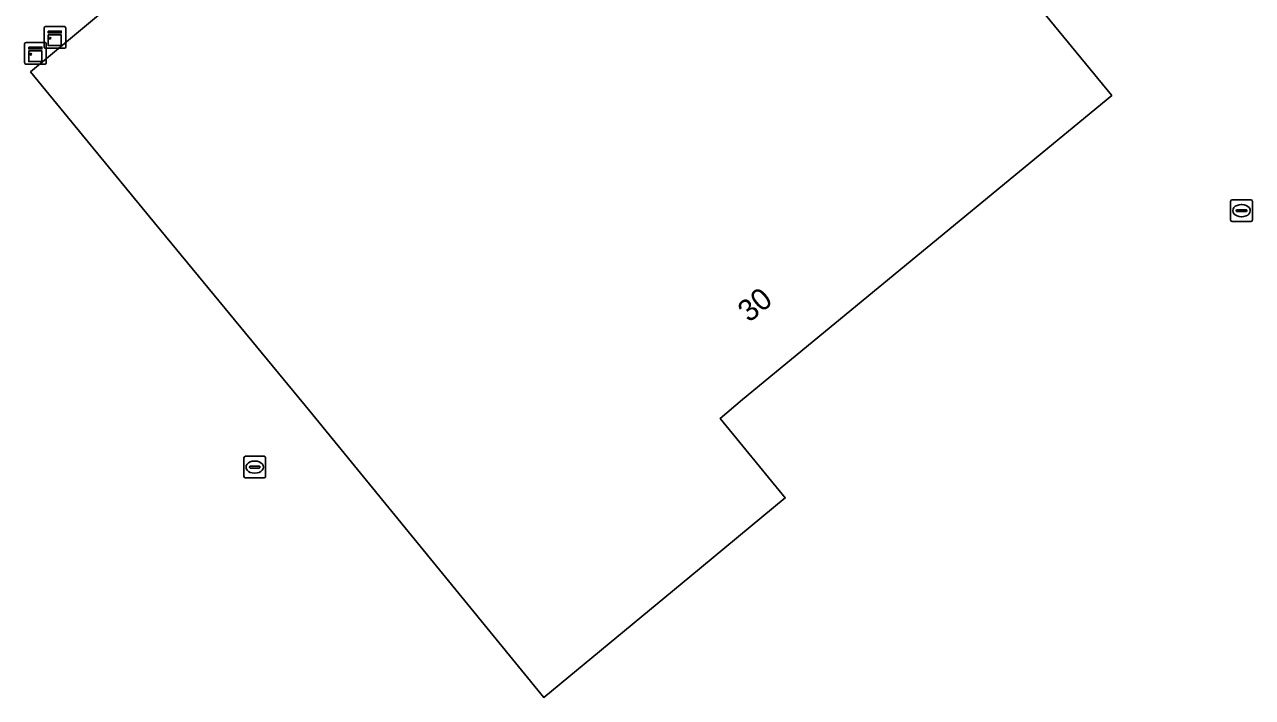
# Model space of a CAD drawing. Extents: x 156141 to 158132, y 385651 to 388333.
# Drawn here: x 157149.6 to 157206.1, y 386304.7 to 386335.6 of the extents above; entities that cross this region are included whole.
import ezdxf

# ---------------------------------------------------------------- set-up
doc = ezdxf.new("R2010")
doc.units = 0
for name, color, linetype in [('IMGEO_Erf', 7, 'Continuous'), ('IMGEO_Kast', 7, 'Continuous'), ('IMGEO_Kolk', 7, 'Continuous'), ('IMGEO_Pand', 7, 'Continuous'), ('IMGEO_Pand_nummerreeks', 7, 'Continuous'), ('IMGEO_Rioolput', 7, 'Continuous')]:
    doc.layers.add(name, color=color, linetype=linetype)

msp = doc.modelspace()

# ---------------------------------------------------------------- linework, layer by layer
at = {"layer": 'IMGEO_Erf'}
msp.add_lwpolyline([(157149.922, 386333.398), (157160.041, 386341.853), (157161.117, 386342.776), (157162.133, 386343.594), (157165.226, 386346.119), (157167.948, 386348.366), (157171.025, 386350.88), (157173.757, 386353.14), (157176.864, 386355.643), (157177.859, 386356.521), (157178.954, 386357.421), (157199.602, 386332.321), (157182.63, 386318.349), (157181.607, 386317.478), (157184.594, 386313.821), (157180.217, 386310.192), (157173.499, 386304.656), (157162.753, 386317.816), (157155.393, 386326.726)], close=True, dxfattribs=at)
at = {"layer": 'IMGEO_Kast'}
for p, q in [((157150.538, 386334.557), (157150.538, 386335.398)), ((157150.538, 386335.398), (157150.538, 386334.557)), ((157150.613, 386335.482), (157151.454, 386335.482)), ((157151.454, 386335.482), (157150.613, 386335.482)), ((157151.538, 386335.407), (157151.538, 386334.566)), ((157151.538, 386334.566), (157151.538, 386335.407)), ((157149.644, 386333.824), (157149.644, 386334.665)), ((157149.644, 386334.665), (157149.644, 386333.824)), ((157149.719, 386334.749), (157150.56, 386334.749)), ((157150.56, 386334.749), (157149.719, 386334.749)), ((157151.463, 386334.482), (157150.622, 386334.482)), ((157150.622, 386334.482), (157151.463, 386334.482)), ((157150.644, 386334.674), (157150.644, 386333.833)), ((157150.644, 386333.833), (157150.644, 386334.674)), ((157150.569, 386333.749), (157149.728, 386333.749)), ((157149.728, 386333.749), (157150.569, 386333.749))]:
    msp.add_line(p, q, dxfattribs=at)
for points in [[(157150.733, 386335.272), (157151.333, 386335.272), (157151.333, 386335.187), (157150.733, 386335.187), (157150.733, 386335.272)], [(157150.733, 386335.097), (157151.333, 386335.097), (157151.333, 386334.608), (157150.733, 386334.608), (157150.733, 386335.097)], [(157149.839, 386334.539), (157150.439, 386334.539), (157150.439, 386334.454), (157149.839, 386334.454), (157149.839, 386334.539)], [(157149.839, 386334.364), (157150.439, 386334.364), (157150.439, 386333.875), (157149.839, 386333.875), (157149.839, 386334.364)]]:
    msp.add_lwpolyline(points, dxfattribs=at)
for centre in [(157150.817, 386334.946), (157149.923, 386334.213)]:
    msp.add_circle(centre, 0.0377, dxfattribs=at)
for centre, start, end in [((157150.616, 386335.404), 92.4484, 184.2845), ((157150.616, 386335.404), 92.4484, 184.2845), ((157151.46, 386335.404), 2.4484, 94.2845), ((157151.46, 386335.404), 2.4484, 94.2845), ((157149.722, 386334.671), 92.4484, 184.2845), ((157149.722, 386334.671), 92.4484, 184.2845), ((157150.616, 386334.56), 182.4484, 274.2845), ((157150.616, 386334.56), 182.4484, 274.2845), ((157150.566, 386334.671), 2.4484, 94.2845), ((157150.566, 386334.671), 2.4484, 94.2845), ((157151.46, 386334.56), 272.4484, 4.2845), ((157151.46, 386334.56), 272.4484, 4.2845), ((157149.722, 386333.827), 182.4484, 274.2845), ((157149.722, 386333.827), 182.4484, 274.2845), ((157150.566, 386333.827), 272.4484, 4.2845), ((157150.566, 386333.827), 272.4484, 4.2845)]:
    msp.add_arc(centre, 0.0779, start, end, dxfattribs=at)
at = {"layer": 'IMGEO_Kolk'}
for p, q in [((157205.062, 386326.597), (157205.062, 386327.449)), ((157205.137, 386327.523), (157205.989, 386327.523)), ((157205.364, 386327.066), (157205.762, 386327.066)), ((157205.55, 386327.303), (157205.575, 386327.303)), ((157206.063, 386327.449), (157206.063, 386326.597)), ((157205.989, 386326.523), (157205.137, 386326.523)), ((157205.321, 386327.017), (157205.321, 386327.029)), ((157205.759, 386326.98), (157205.361, 386326.98)), ((157205.573, 386326.743), (157205.548, 386326.743)), ((157205.805, 386327.029), (157205.805, 386327.017))]:
    msp.add_line(p, q, dxfattribs=at)
for points in [[(157205.062, 386326.597), (157205.062, 386327.449)], [(157205.137, 386327.523), (157205.989, 386327.523)], [(157206.063, 386327.449), (157206.063, 386326.597)], [(157205.989, 386326.523), (157205.137, 386326.523)]]:
    msp.add_lwpolyline(points, dxfattribs=at)
for centre, radius, start, end in [((157205.139, 386327.447), 0.0765, 91.552, 178.448), ((157205.139, 386327.447), 0.0765, 91.552, 178.448), ((157205.361, 386327.026), 0.0403, 85.8775, 175.7526), ((157205.766, 386327.028), 0.0386, 1.7309, 96.639), ((157205.987, 386327.447), 0.0765, 1.552, 88.448), ((157205.987, 386327.447), 0.0765, 1.552, 88.448), ((157205.139, 386326.599), 0.0765, 181.552, 268.448), ((157205.139, 386326.599), 0.0765, 181.552, 268.448), ((157205.358, 386327.016), 0.0366, 178.938, 274.7102), ((157205.762, 386327.023), 0.043, 264.8664, 352.4533), ((157205.987, 386326.599), 0.0765, 271.552, 358.448), ((157205.987, 386326.599), 0.0765, 271.552, 358.448)]:
    msp.add_arc(centre, radius, start, end, dxfattribs=at)
for centre, major_axis, ratio, start_param, end_param in [((157205.549, 386327.023), (-0.387, 0.002), 0.722429, 4.712389, 7.853982), ((157205.574, 386327.023), (-0.39, 0.002), 0.717154, 1.570796, 4.712389)]:
    msp.add_ellipse(centre, major_axis=major_axis, ratio=ratio, start_param=start_param, end_param=end_param, dxfattribs=at)
at = {"layer": 'IMGEO_Pand'}
msp.add_lwpolyline([(157161.117, 386342.776), (157160.041, 386341.853), (157149.922, 386333.398), (157155.393, 386326.726), (157162.753, 386317.816), (157173.499, 386304.656), (157180.217, 386310.192), (157184.594, 386313.821), (157181.607, 386317.478), (157182.63, 386318.349), (157199.602, 386332.321), (157178.954, 386357.421), (157177.859, 386356.521), (157176.864, 386355.643), (157173.757, 386353.14), (157171.025, 386350.88), (157167.948, 386348.366), (157165.226, 386346.119), (157162.133, 386343.594)], close=True, dxfattribs=at)
at = {"layer": 'IMGEO_Rioolput'}
for p, q in [((157159.72, 386314.814), (157159.72, 386315.666)), ((157159.795, 386315.74), (157160.647, 386315.74)), ((157159.979, 386315.234), (157159.979, 386315.246)), ((157160.417, 386315.197), (157160.019, 386315.197)), ((157160.022, 386315.283), (157160.42, 386315.283)), ((157160.208, 386315.52), (157160.233, 386315.52)), ((157160.463, 386315.246), (157160.463, 386315.234)), ((157160.721, 386315.666), (157160.721, 386314.814)), ((157160.647, 386314.74), (157159.795, 386314.74)), ((157160.231, 386314.96), (157160.206, 386314.96))]:
    msp.add_line(p, q, dxfattribs=at)
for points in [[(157159.72, 386314.814), (157159.72, 386315.666)], [(157159.795, 386315.74), (157160.647, 386315.74)], [(157160.721, 386315.666), (157160.721, 386314.814)], [(157160.647, 386314.74), (157159.795, 386314.74)]]:
    msp.add_lwpolyline(points, dxfattribs=at)
for centre, radius, start, end in [((157159.797, 386315.664), 0.0765, 91.552, 178.448), ((157159.797, 386315.664), 0.0765, 91.552, 178.448), ((157160.019, 386315.243), 0.0403, 85.8775, 175.7526), ((157160.016, 386315.233), 0.0366, 178.938, 274.7102), ((157160.42, 386315.24), 0.043, 264.8664, 352.4533), ((157160.424, 386315.245), 0.0386, 1.7309, 96.639), ((157160.645, 386315.664), 0.0765, 1.552, 88.448), ((157160.645, 386315.664), 0.0765, 1.552, 88.448), ((157159.797, 386314.816), 0.0765, 181.552, 268.448), ((157159.797, 386314.816), 0.0765, 181.552, 268.448), ((157160.645, 386314.816), 0.0765, 271.552, 358.448), ((157160.645, 386314.816), 0.0765, 271.552, 358.448)]:
    msp.add_arc(centre, radius, start, end, dxfattribs=at)
for centre, major_axis, ratio, start_param, end_param in [((157160.207, 386315.24), (-0.387, 0.002), 0.722429, 4.712389, 7.853982), ((157160.232, 386315.24), (-0.39, 0.002), 0.717154, 1.570796, 4.712389)]:
    msp.add_ellipse(centre, major_axis=major_axis, ratio=ratio, start_param=start_param, end_param=end_param, dxfattribs=at)

# ---------------------------------------------------------------- texts
at = {"layer": 'IMGEO_Pand_nummerreeks'}
msp.add_text('30', height=1, rotation=39.6, dxfattribs=at).set_placement((157182.939, 386321.851))

doc.saveas('drawing.dxf')
